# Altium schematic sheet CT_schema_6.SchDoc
size 479 x 328 mm
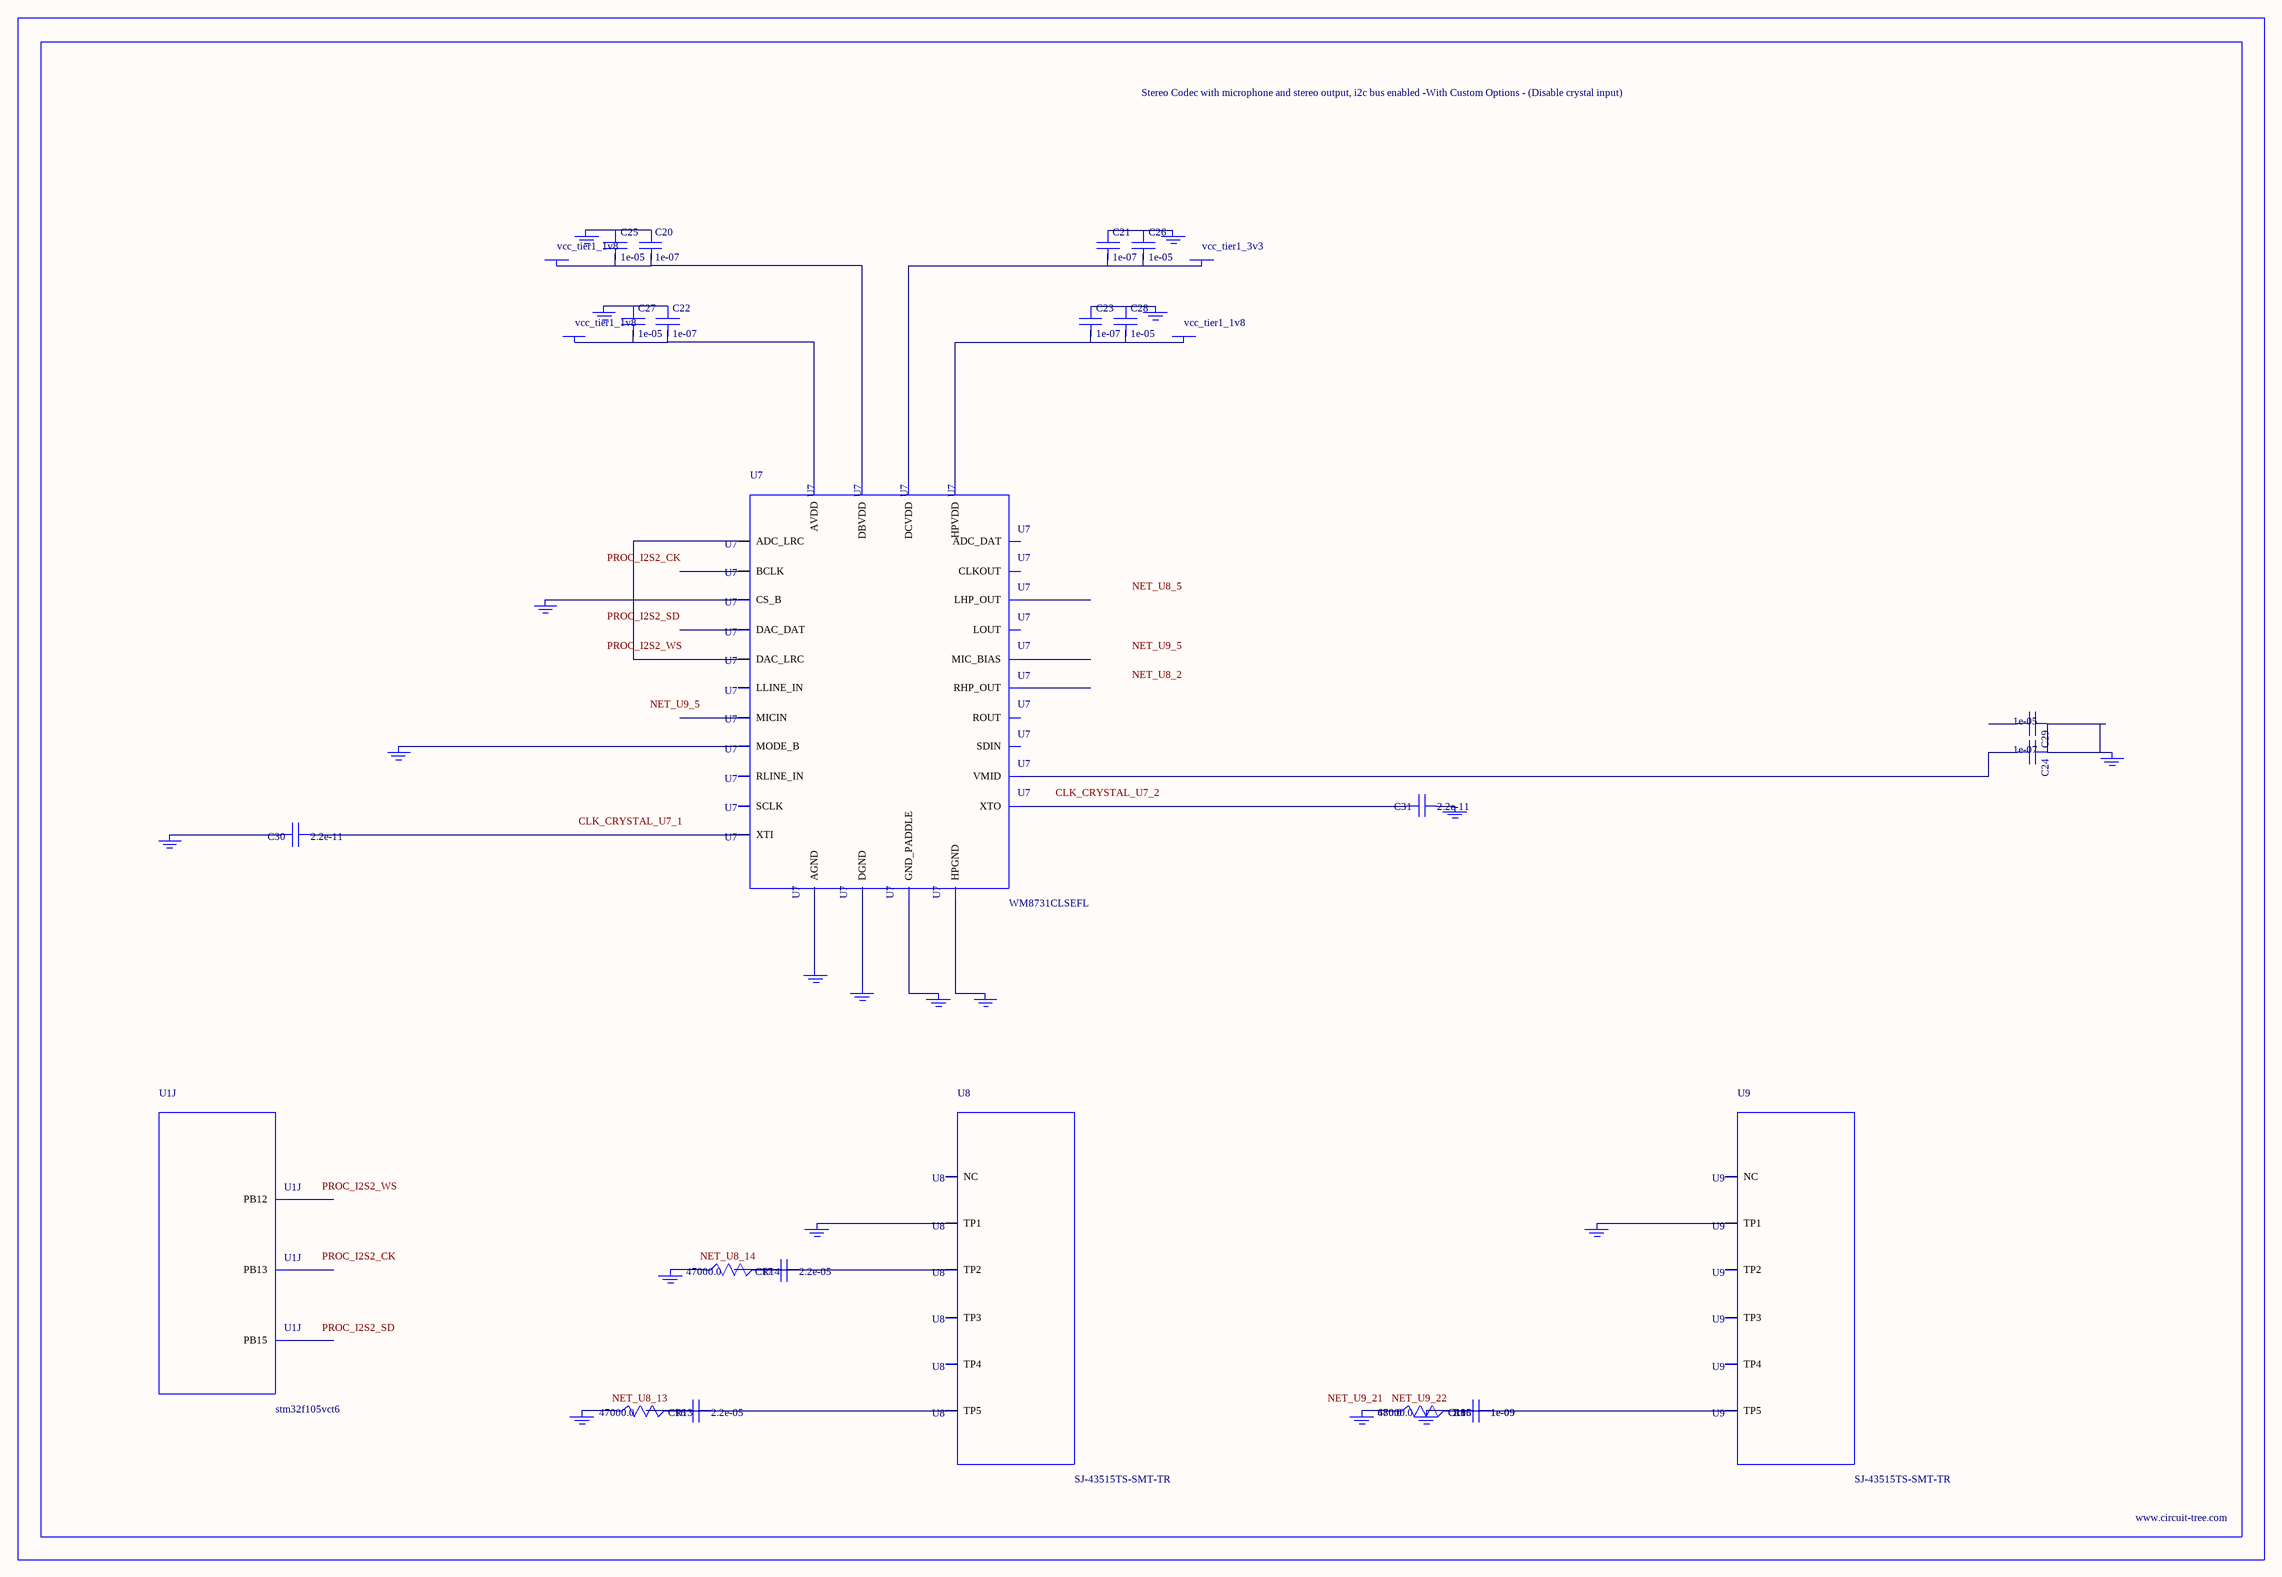
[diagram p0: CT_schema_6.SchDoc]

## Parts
BORDER5  (no value)
C16  2.2e-05  [C1210]
C17  2.2e-05  [C1210]
C18  1e-09  [C0402]
C19  1e-09  [C0402]
C20  1e-07  [C0402]
C21  1e-07  [C0402]
C22  1e-07  [C0402]
C23  1e-07  [C0402]
C24  1e-07  [C0402]
C25  1e-05  [C0805]
C26  1e-05  [C0805]
C27  1e-05  [C0805]
C28  1e-05  [C0805]
C29  1e-05  [C0805]
C30  2.2e-11  [C0402]
C31  2.2e-11  [C0402]
GND_INSTANCE_5_0  (no value)
GND_INSTANCE_5_1  (no value)
GND_INSTANCE_5_2  (no value)
GND_INSTANCE_5_3  (no value)
GND_INSTANCE_5_4  (no value)
GND_INSTANCE_5_5  (no value)
GND_INSTANCE_5_6  (no value)
GND_INSTANCE_5_7  (no value)
GND_INSTANCE_5_8  (no value)
GND_INSTANCE_5_9  (no value)
GND_INSTANCE_5_10  (no value)
GND_INSTANCE_5_11  (no value)
GND_INSTANCE_5_12  (no value)
GND_INSTANCE_5_13  (no value)
GND_INSTANCE_5_14  (no value)
GND_INSTANCE_5_15  (no value)
GND_INSTANCE_5_16  (no value)
GND_INSTANCE_5_17  (no value)
GND_INSTANCE_5_18  (no value)
POWER_INSTANCE_5_0  vcc_tier1_3v3
POWER_INSTANCE_5_1  vcc_tier1_1v8
POWER_INSTANCE_5_2  vcc_tier1_1v8
POWER_INSTANCE_5_3  vcc_tier1_1v8
R13  47000.0  [R0603]
R14  47000.0  [R0603]
R15  47000.0  [R0603]
R16  680.0  [R0603]
U1  stm32f105vct6  [LQFP100]  (part J of 10)
U7  WM8731CLSEFL  [QFN-28]
U8  SJ-43515TS-SMT-TR  [SJ-43515TS-SMT-TR]
U9  SJ-43515TS-SMT-TR  [SJ-43515TS-SMT-TR]

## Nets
NetC16_1: C16.1 C16.2 R13.2 U8.5(TP5)
NetC17_1: C17.1 C17.2 R14.2 U8.2(TP2)
NetC18_1: C18.1 C18.2 C19.1 C19.2 GND_INSTANCE_5_18.0(GND) R15.2 R16.2 U9.5(TP5)
NetC20_1: C20.1 C25.1 GND_INSTANCE_5_3.0(GND)
NetC20_2: C20.2 C25.2 POWER_INSTANCE_5_1.0(PWR) U7.5(DBVDD)
NetC21_1: C21.1 C26.1 GND_INSTANCE_5_2.0(GND)
NetC21_2: C21.2 C26.2 POWER_INSTANCE_5_0.0(PWR) U7.3(DCVDD)
NetC22_1: C22.1 C27.1 GND_INSTANCE_5_6.0(GND)
NetC22_2: C22.2 C27.2 POWER_INSTANCE_5_3.0(PWR) U7.18(AVDD)
NetC23_1: C23.1 C28.1 GND_INSTANCE_5_4.0(GND)
NetC23_2: C23.2 C28.2 POWER_INSTANCE_5_2.0(PWR) U7.12(HPVDD)
NetC24_1: C24.1 C29.1 GND_INSTANCE_5_7.0(GND)
NetC24_2: C24.2 U7.20(VMID)
NetC30_1: C30.1 U7.1(XTI)
NetC30_2: C30.2 GND_INSTANCE_5_0.0(GND)
NetC31_1: C31.1 GND_INSTANCE_5_1.0(GND)
NetC31_2: C31.2 U7.2(XTO)
NetGND_INSTANCE_5_5_0: GND_INSTANCE_5_5.0(GND) U7.15(HPGND)
NetGND_INSTANCE_5_8_0: GND_INSTANCE_5_8.0(GND) U7.25(MODE_B)
NetGND_INSTANCE_5_9_0: GND_INSTANCE_5_9.0(GND) U7.26(CS_B)
NetGND_INSTANCE_5_10_0: GND_INSTANCE_5_10.0(GND) U7.29(GND_PADDLE)
NetGND_INSTANCE_5_11_0: GND_INSTANCE_5_11.0(GND) U7.4(DGND)
NetGND_INSTANCE_5_12_0: GND_INSTANCE_5_12.0(GND) U7.19(AGND)
NetGND_INSTANCE_5_13_0: GND_INSTANCE_5_13.0(GND) U8.1(TP1)
NetGND_INSTANCE_5_14_0: GND_INSTANCE_5_14.0(GND) R14.1
NetGND_INSTANCE_5_15_0: GND_INSTANCE_5_15.0(GND) R13.1
NetGND_INSTANCE_5_16_0: GND_INSTANCE_5_16.0(GND) U9.1(TP1)
NetGND_INSTANCE_5_17_0: GND_INSTANCE_5_17.0(GND) R15.1 R16.1
NetU7_9: U7.9(DAC_LRC) U7.11(ADC_LRC)

Not connected (* = marked no-connect by the designer): C29 2; U1 51(PB12) 52(PB13) 54(PB15); U7 6(CLKOUT) 7(BCLK) 8(DAC_DAT) 10(ADC_DAT) 13(LHP_OUT) 14(RHP_OUT) 16(LOUT) 17(ROUT) 21(MIC_BIAS) 22(MICIN) 23(RLINE_IN) 24(LLINE_IN) 27(SDIN) 28(SCLK); U8 3(TP3) 4(TP4) 6(NC); U9 2(TP2) 3(TP3) 4(TP4) 6(NC)

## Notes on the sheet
- Labels drawn without touching a wire or pin: CLK_CRYSTAL_U7_1, CLK_CRYSTAL_U7_2, NET_U8_2, NET_U8_5, NET_U8_13, NET_U8_14, NET_U9_5, NET_U9_21, NET_U9_22, PROC_I2S2_CK, PROC_I2S2_SD, PROC_I2S2_WS

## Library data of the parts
BORDER5 = BORDER_PAGE5
C16 C17 = C1210C224K5RACTU
C18 C19 = C0402C102K3RAC
C20-C24 = C0402C104K3RACTU
C25-C29 = C0805C106K8RACTU
C30 C31 = C0402C220K3RAC
GND_INSTANCE_5_0-GND_INSTANCE_5_18 = GND
POWER_INSTANCE_5_0-POWER_INSTANCE_5_3 = PWR
R13-R15 = RC0603JR-0747KL
R16 = RC0603JR-07680RL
